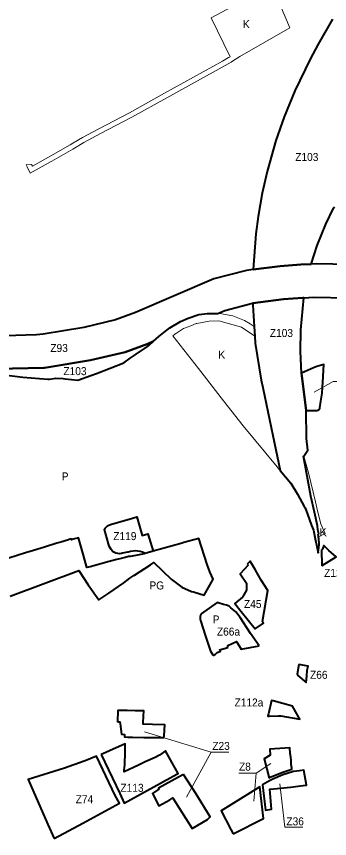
# Model space of a CAD drawing. Extents: x -650276 to -642489, y -1074311 to -1066658.
# Drawn here: x -648750 to -647810, y -1070673 to -1068210 of the extents above; entities that cross this region are included whole.
import ezdxf

# ---------------------------------------------------------------- set-up
doc = ezdxf.new("R2010")
doc.units = 0
doc.header["$LTSCALE"] = 9.6
for name, color, linetype, lineweight in [('2', 7, 'Continuous', 40), ('3', 7, 'Continuous', 40), ('44', 7, 'Continuous', 40), ('45', 7, 'Continuous', 40), ('46', 7, 'Continuous', 13), ('47', 7, 'Continuous', 13), ('48', 7, 'Continuous', 35), ('59', 7, 'Continuous', 13), ('60', 7, 'Continuous', 35)]:
    doc.layers.add(name, color=color, linetype=linetype, lineweight=lineweight)

msp = doc.modelspace()

# ---------------------------------------------------------------- linework, layer by layer
at = {"layer": '2'}
for points in [[(-648338.933, -1069812.492), (-648363.563, -1069819.352), (-648371.093, -1069815.602), (-648377.983, -1069813.332), (-648385.093, -1069811.952), (-648392.333, -1069811.482), (-648399.563, -1069811.922), (-648406.723, -1069813.272), (-648414.54, -1069815.288), (-648415.873, -1069815.632), (-648430.764, -1069818.704), (-648433.853, -1069819.342), (-648439.773, -1069820.012), (-648445.683, -1069819.552), (-648451.413, -1069818.022), (-648456.763, -1069815.432), (-648461.523, -1069811.902), (-648465.553, -1069807.532), (-648468.703, -1069802.482), (-648470.853, -1069796.942), (-648480.15, -1069765.358), (-648485.323, -1069747.432), (-648485.023, -1069746.592), (-648483.157, -1069743.818), (-648481.673, -1069741.612), (-648477.273, -1069737.482), (-648475.905, -1069736.566), (-648472.283, -1069734.142), (-648464.333, -1069730.932), (-648439.683, -1069724.232), (-648401.171, -1069713.196), (-648388.514, -1069709.779), (-648372.522, -1069765.283), (-648354.898, -1069760.328)], [(-647833.172, -1069855.944), (-647833.172, -1069855.944), (-647831.62, -1069854.99), (-647789.55, -1069829.12), (-647811.83, -1069810.39), (-647827.16, -1069795.32), (-647831.32, -1069806.56), (-647833.91, -1069808.91), (-647833.2, -1069854.15)]]:
    msp.add_lwpolyline(points, close=True, dxfattribs=at)
at = {"layer": '3'}
msp.add_lwpolyline([(-648495.666, -1070421.476), (-648439.409, -1070538.729), (-648425.835, -1070567.021), (-648267.801, -1070480.55), (-648263.859, -1070478.393), (-648282.01, -1070446.35), (-648302.01, -1070411.05), (-648320.24, -1070423.64), (-648332.97, -1070430.18), (-648362.79, -1070443.63), (-648363.1, -1070443.1), (-648383.61, -1070453.86), (-648426.05, -1070473.34), (-648425.71, -1070468.87), (-648424.47, -1070452.7), (-648423.56, -1070413.35), (-648423.005, -1070389.357), (-648469.77, -1070410.47), (-648481.18, -1070415.62)], close=True, dxfattribs=at)
at = {"layer": '44'}
for points in [[(-647801.168, -1068218.237), (-647843.6, -1068292.629), (-647868.214, -1068337.803), (-647914.339, -1068432.512), (-647946.187, -1068510.254), (-647971.074, -1068581.98), (-647997.27, -1068674.747), (-648011.775, -1068739.718), (-648023.914, -1068809.332), (-648030.73, -1068861.213), (-648038.596, -1068968.281), (-647958.168, -1068957.73)], [(-647864.531, -1068951.823), (-647846.989, -1068896.545), (-647820.883, -1068832.117), (-647797.632, -1068784.713), (-647795.185, -1068780.485)], [(-648058.764, -1068970.927), (-648156.739, -1068996.273), (-648392.002, -1069097.554), (-648451.865, -1069119.456), (-648547.243, -1069141.81), (-648668.959, -1069161.838), (-648688.912, -1069163.603), (-648721.315, -1069164.952), (-648781.015, -1069167.44)], [(-647749.978, -1068953.416), (-647850.043, -1068951.099), (-647864.531, -1068951.823), (-647895.901, -1068953.392), (-647958.168, -1068957.73), (-648038.596, -1068968.281), (-648038.596, -1068968.281), (-648038.746, -1068968.301), (-648058.764, -1068970.927)], [(-647958.168, -1068957.73), (-647895.901, -1068953.392), (-647864.531, -1068951.823)], [(-648665.007, -1069262.694), (-648527.693, -1069239.938), (-648423.173, -1069215.44), (-648354.978, -1069190.492), (-648338.523, -1069183.389), (-648322.14, -1069168.56), (-648306.83, -1069156.57), (-648289.25, -1069142.79), (-648257.5, -1069124.41), (-648234.22, -1069113.6), (-648202.46, -1069103.3), (-648175.65, -1069099.64), (-648144.866, -1069099.987), (-648124.327, -1069091.181), (-648040.705, -1069069.547), (-648040.456, -1069069.483)], [(-648040.456, -1069069.483), (-648040.537, -1069075.531), (-648036.291, -1069139.458), (-648034.421, -1069167.61)], [(-648040.456, -1069069.483), (-648039.666, -1069069.279), (-647948.18, -1069057.276)], [(-647948.18, -1069057.276), (-648039.666, -1069069.279), (-648040.456, -1069069.483)], [(-647948.18, -1069057.276), (-647889.927, -1069053.218), (-647886.615, -1069053.052)], [(-647886.615, -1069053.052), (-647889.927, -1069053.218), (-647948.18, -1069057.276)], [(-647887.087, -1069527.229), (-647878.73, -1069515.45), (-647874.75, -1069509.84), (-647878.93, -1069475.09), (-647880.326, -1069390.832), (-647893.553, -1069279.021), (-647896.67, -1069213.573), (-647896.362, -1069149.171), (-647886.615, -1069053.052)], [(-647886.615, -1069053.052), (-647856.541, -1069051.548), (-647756.441, -1069053.207), (-647708.401, -1069056.275), (-647511.94, -1069076.703), (-647426.417, -1069084.624), (-647344.902, -1069091.02), (-647270.522, -1069094.255), (-647197.498, -1069094.255), (-647123.648, -1069091.043), (-647065.688, -1069087.73)], [(-648034.421, -1069167.61), (-648033, -1069189), (-648015, -1069300), (-648010.092, -1069322.087), (-647980.331, -1069465.915), (-647958.34, -1069570.699), (-647925.99, -1069608.57)], [(-648354.978, -1069190.492), (-648423.173, -1069215.44), (-648527.693, -1069239.938), (-648652.716, -1069260.657)], [(-648526.15, -1069286.21), (-648508.95, -1069280.01), (-648427.08, -1069247.75), (-648407.73, -1069233.88), (-648389.91, -1069221.86), (-648355.81, -1069198.88), (-648351.77, -1069195.88), (-648338.523, -1069183.389), (-648354.978, -1069190.492)], [(-648918.889, -1069268.875), (-648761.189, -1069265.035), (-648666.827, -1069262.738), (-648665.007, -1069262.694)], [(-648666.827, -1069262.738), (-648761.189, -1069265.035), (-648918.889, -1069268.875), (-648909.86, -1069270.02), (-648861.49, -1069275.34), (-648785.92, -1069284.2), (-648730.66, -1069290.43), (-648730.66, -1069290.43), (-648655.53, -1069297.18), (-648650.06, -1069296.39), (-648636.85, -1069294.49)], [(-648652.716, -1069260.657), (-648665.007, -1069262.694), (-648666.827, -1069262.738)], [(-648636.85, -1069294.49), (-648630.82, -1069293.63), (-648609.425, -1069295.033), (-648603.228, -1069295.53), (-648565.18, -1069299.46), (-648526.15, -1069286.21)], [(-647865.69, -1069647.32), (-647887.649, -1069528.021), (-647887.087, -1069527.229)], [(-647925.99, -1069608.57), (-647906.16, -1069641.48), (-647885.665, -1069678.788), (-647885.663, -1069678.794), (-647883.51, -1069682.71), (-647875.82, -1069701.85)], [(-647842.438, -1069760.647), (-647845.086, -1069748.753), (-647846.484, -1069736.663), (-647855.158, -1069695.232), (-647865.69, -1069647.32)], [(-647875.82, -1069701.85), (-647864.19, -1069735.12), (-647858.44, -1069749.43), (-647852.63, -1069775.7), (-647850.66, -1069785.74), (-647849.165, -1069793.367), (-647843.74, -1069817.63), (-647841.402, -1069792.351)], [(-647841.402, -1069792.351), (-647842.489, -1069773.282), (-647842.622, -1069770.956), (-647843.337, -1069769.013), (-647843.443, -1069768.293), (-647843.458, -1069768.256), (-647843.449, -1069768.252), (-647844.371, -1069761.991), (-647842.438, -1069760.647)]]:
    msp.add_lwpolyline(points, dxfattribs=at)
msp.add_lwpolyline([(-647860.52, -1069390.72), (-647848.24, -1069390.65), (-647845.25, -1069390.07), (-647843.41, -1069389.23), (-647841.81, -1069387.99), (-647840.42, -1069386.51), (-647839.4, -1069384.73), (-647838.79, -1069382.86), (-647836.2, -1069362.68), (-647832.29, -1069338.58), (-647832.29, -1069338.58), (-647831.19, -1069320.69), (-647830.23, -1069305.38), (-647826.928, -1069253.199), (-647848.17, -1069259.21), (-647858.37, -1069263.03), (-647893.553, -1069279.017), (-647880.326, -1069390.832)], close=True, dxfattribs=at)
at = {"layer": '44', "lineweight": 13}
msp.add_lwpolyline([(-647751.811, -1069303.761), (-647798.61, -1069303.761), (-647856.005, -1069335.572)], dxfattribs=at)
msp.add_lwpolyline([(-647751.811, -1069303.761), (-647798.61, -1069303.761), (-647856.005, -1069335.572)], dxfattribs=at)
at = {"layer": '44'}
msp.add_arc((-648354.978, -1069190.492), 0.000000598, 264.13978, 298.69712, dxfattribs=at)
at = {"layer": '45'}
for points in [[(-648767.83, -1069946.87), (-648562.242, -1069870.301), (-648533.79, -1069913.49), (-648502.048, -1069957.969), (-648472.6, -1069937.81), (-648426.82, -1069906.88), (-648409.44, -1069893.25), (-648396.87, -1069885.43), (-648395.03, -1069884.22), (-648347.06, -1069853), (-648337.48, -1069846.531), (-648285.62, -1069895.71), (-648253.13, -1069919.7), (-648223.99, -1069932.96), (-648218.245, -1069934.595), (-648186.268, -1069943.697), (-648160.04, -1069897.73), (-648159.1, -1069896.39), (-648169.15, -1069873.81), (-648176.78, -1069851.74), (-648201.83, -1069773.86), (-648247.27, -1069786.64), (-648251.94, -1069787.95), (-648339.05, -1069812.45), (-648363.68, -1069819.31), (-648365.81, -1069819.9), (-648391.08, -1069825.45), (-648408.45, -1069827.83), (-648412.74, -1069828.72), (-648422.75, -1069830.78), (-648435.53, -1069834.44), (-648447.98, -1069837.44), (-648470.79, -1069843.51), (-648528.11, -1069858.73), (-648537.86, -1069861.22), (-648541.06, -1069849.78), (-648546.97, -1069828.68), (-648562.87, -1069771.85), (-648579.63, -1069776.66), (-648584.65, -1069778.1), (-648586.09, -1069775.75), (-648593.59, -1069778.06), (-648615.88, -1069784.93), (-648627.99, -1069788.67), (-648665.05, -1069799.99), (-648698.31, -1069810.16), (-648722.24, -1069817.54), (-648772.48, -1069832.83)], [(-648128.48, -1069971.7), (-648140.96, -1069968.01), (-648147.46, -1069966.19), (-648194.84, -1070000.49)], [(-648111.44, -1069977.32), (-648118.75, -1069974.53), (-648128.48, -1069971.7)], [(-648021.35, -1070096.14), (-648046.83, -1070058.62), (-648077.68, -1070011.06), (-648091.06, -1069994.07), (-648105.79, -1069981.56), (-648111.44, -1069977.32)], [(-648194.84, -1070000.49), (-648197.19, -1070003.94), (-648198.17, -1070008.05), (-648198.48, -1070012.3), (-648198.22, -1070016.4), (-648197.23, -1070020.37), (-648182.01, -1070067.11)], [(-648182.01, -1070067.11), (-648167.48, -1070111.75), (-648159.89, -1070122.49), (-648159.02, -1070123.71), (-648156.07, -1070123.54)], [(-648152.35, -1070121.05), (-648147.02, -1070116.35), (-648139.45, -1070112.79), (-648136.61, -1070111.97), (-648139.91, -1070107.48), (-648115.11, -1070101.26)], [(-648115.11, -1070101.26), (-648114.7, -1070094.68), (-648089.22, -1070083.27), (-648074.76, -1070106.17), (-648021.35, -1070096.14)], [(-648156.07, -1070123.54), (-648153.85, -1070122.38), (-648152.35, -1070121.05)]]:
    msp.add_lwpolyline(points, dxfattribs=at)
for points in [[(-648057.11, -1069851.12), (-648053.61, -1069854.64), (-648078.54, -1069880.01), (-648059.32, -1069908.27), (-648059.5, -1069929.52), (-648071.58, -1069950.39), (-648093.67, -1069969.42), (-648074.96, -1069993.46), (-648032.85, -1070044.73), (-648008.18, -1070028.25), (-648010.44, -1070023.66), (-648010.94, -1070022.65), (-647994.71, -1069930.53), (-648015.11, -1069898.98), (-648032.94, -1069867.46), (-648048.08, -1069841.95)], [(-648057.11, -1069851.12), (-648053.61, -1069854.64), (-648078.54, -1069880.01), (-648059.32, -1069908.27), (-648059.5, -1069929.52), (-648071.58, -1069950.39), (-648093.67, -1069969.42), (-648074.96, -1069993.46), (-648032.85, -1070044.73), (-648008.18, -1070028.25), (-648010.44, -1070023.66), (-648010.94, -1070022.65), (-647994.71, -1069930.53), (-648015.11, -1069898.98), (-648032.94, -1069867.46), (-648048.08, -1069841.95)], [(-647902.17, -1070151.64), (-647906.6, -1070180.65), (-647905.17, -1070184.5), (-647879.81, -1070206.08), (-647878.18, -1070186.33), (-647876.74, -1070168.88), (-647873.97, -1070156.58)], [(-647902.17, -1070151.64), (-647906.6, -1070180.65), (-647905.17, -1070184.5), (-647879.81, -1070206.08), (-647878.18, -1070186.33), (-647876.74, -1070168.88), (-647873.97, -1070156.58)], [(-647962.82, -1070305.9), (-647956.36, -1070305.77), (-647898.82, -1070315.51), (-647921.51, -1070276.76), (-647979.24, -1070260.71), (-647983.6, -1070259.5), (-647992.71, -1070300.01), (-647995.46, -1070306.55), (-647991.12, -1070306.46)], [(-648444.85, -1070324.47), (-648444.15, -1070289.16), (-648428.98, -1070288.92), (-648416.93, -1070288.85), (-648392.94, -1070289.25), (-648368.25, -1070289.71), (-648370.07, -1070325.94), (-648370.07, -1070329.902), (-648341.46, -1070330.48), (-648305.47, -1070331.23), (-648307.13, -1070365.57), (-648307.67, -1070371.78), (-648367.67, -1070371.16), (-648401.35, -1070370.5), (-648414.75, -1070370.24), (-648424.05, -1070370), (-648424.31, -1070362.21), (-648433.46, -1070361.94), (-648437.65, -1070328.8), (-648438.296, -1070324.598)], [(-648444.85, -1070324.47), (-648444.15, -1070289.16), (-648428.98, -1070288.92), (-648416.93, -1070288.85), (-648392.94, -1070289.25), (-648368.25, -1070289.71), (-648370.07, -1070325.94), (-648370.07, -1070329.902), (-648341.46, -1070330.48), (-648305.47, -1070331.23), (-648307.13, -1070365.57), (-648307.67, -1070371.78), (-648367.67, -1070371.16), (-648401.35, -1070370.5), (-648414.75, -1070370.24), (-648424.05, -1070370), (-648424.31, -1070362.21), (-648433.46, -1070361.94), (-648437.65, -1070328.8), (-648438.296, -1070324.598)], [(-647991.539, -1070492.016), (-647985.19, -1070488.804), (-647953.251, -1070475.276), (-647923.247, -1070465.749), (-647923.53, -1070462.75), (-647924.63, -1070451.09), (-647925.5, -1070439.63), (-647926.53, -1070429.76), (-647927.67, -1070418.74), (-647929.24, -1070401.97), (-647988.86, -1070405.95), (-647988.11, -1070423.93), (-648005.668, -1070434.145)], [(-648636.757, -1070673.431), (-648550.72, -1070626.869), (-648440.531, -1070567.236), (-648452.97, -1070544.21), (-648509.227, -1070426.957), (-648526.28, -1070433.85), (-648538.611, -1070438.388), (-648546.377, -1070441.246), (-648604.92, -1070462.79), (-648714.161, -1070496.376), (-648655.178, -1070631.294)], [(-647950.48, -1070482.79), (-647980.4, -1070495.463), (-647990.295, -1070500.352), (-648003.85, -1070508.218), (-648010.831, -1070512.588), (-648002, -1070588), (-647984.03, -1070585.46), (-647989.5, -1070525.73), (-647987.436, -1070525.508), (-647977.41, -1070524.43), (-647927.14, -1070519), (-647889.27, -1070514.92), (-647879.89, -1070513.91), (-647879.16, -1070513.83), (-647887.08, -1070468.54), (-647899.87, -1070470.04), (-647917.98, -1070472.47)], [(-648247.67, -1070481.57), (-648262.69, -1070489.67), (-648323.59, -1070522.48), (-648322.18, -1070525.44), (-648341.41, -1070538.42), (-648322.16, -1070575.76), (-648289.22, -1070557.15), (-648279.736, -1070551.783), (-648278.89, -1070553.14), (-648222.58, -1070643.48), (-648176.54, -1070616.09), (-648168.575, -1070607.847), (-648211, -1070538)], [(-648247.67, -1070481.57), (-648262.69, -1070489.67), (-648323.59, -1070522.48), (-648322.18, -1070525.44), (-648341.41, -1070538.42), (-648322.16, -1070575.76), (-648289.22, -1070557.15), (-648279.736, -1070551.783), (-648278.89, -1070553.14), (-648222.58, -1070643.48), (-648176.54, -1070616.09), (-648168.575, -1070607.847), (-648211, -1070538)], [(-648098.637, -1070659.682), (-648007.838, -1070612.851), (-648019, -1070518), (-648135.47, -1070590.61), (-648105.98, -1070645.91)]]:
    msp.add_lwpolyline(points, close=True, dxfattribs=at)
at = {"layer": '46'}
for p, q in [((-648165.109, -1070414.543), (-648239.52, -1070549.62)), ((-648165.109, -1070414.543), (-648239.52, -1070549.62)), ((-648030.462, -1070477.049), (-648036.992, -1070561.483)), ((-647944.293, -1070639.492), (-647959.279, -1070509.201)), ((-647890.215, -1070639.492), (-647944.293, -1070639.492)), ((-647890.215, -1070639.492), (-647904.43, -1070639.492))]:
    msp.add_line(p, q, dxfattribs=at)
for points in [[(-648112.329, -1070414.543), (-648165.109, -1070414.543), (-648364.98, -1070353.932)], [(-648112.329, -1070414.543), (-648165.109, -1070414.543), (-648364.98, -1070353.932)], [(-648081.63, -1070477.049), (-648030.462, -1070477.049), (-647985.902, -1070448.995)]]:
    msp.add_lwpolyline(points, dxfattribs=at)
at = {"layer": '47'}
msp.add_line((-648108.158, -1068330.583), (-648112.198, -1068333.037), dxfattribs=at)
for points in [[(-648101.42, -1068344.28), (-648079.33, -1068330.03), (-647929.45, -1068244.16), (-647971.35, -1068144.48), (-647982.969, -1068116.575), (-648165.28, -1068214.465), (-648108.158, -1068330.583)], [(-648112.198, -1068333.037), (-648112.92, -1068333.424), (-648131.034, -1068344.388), (-648305.242, -1068440.3), (-648410.111, -1068498.408), (-648503.768, -1068547.914), (-648551.041, -1068573.16)], [(-648547.25, -1068588.14), (-648496.73, -1068561.16), (-648402.97, -1068511.6), (-648297.99, -1068453.43), (-648123.53, -1068357.38), (-648105.49, -1068346.46), (-648101.42, -1068344.28)], [(-648551.041, -1068573.16), (-648580.062, -1068590.087), (-648588.022, -1068594.571), (-648653.034, -1068631.191), (-648701.568, -1068658.36), (-648703.816, -1068653.711), (-648720.238, -1068654.205)], [(-648720.238, -1068654.205), (-648717.32, -1068660.24), (-648708.14, -1068679.23), (-648645.69, -1068644.27), (-648643.654, -1068643.123), (-648580.66, -1068607.64), (-648547.25, -1068588.14)], [(-648036.291, -1069139.458), (-648040.537, -1069075.531), (-648040.5, -1069072.79), (-648040.705, -1069069.548), (-648124.327, -1069091.181), (-648144.866, -1069099.987)], [(-648144.866, -1069099.987), (-648139.27, -1069100.05), (-648100.37, -1069107.1), (-648100.37, -1069107.1), (-648065.16, -1069121.12)], [(-648065.16, -1069121.12), (-648048.06, -1069130.81), (-648036.291, -1069139.458)]]:
    msp.add_lwpolyline(points, dxfattribs=at)
for points in [[(-648127.77, -1069361.38), (-648068.71, -1069436.57), (-647967.53, -1069559.94), (-647958.214, -1069571.3), (-647980.331, -1069465.915), (-648010.092, -1069322.087), (-648015, -1069300), (-648033, -1069189), (-648034.421, -1069167.61), (-648073.66, -1069140.86), (-648141.92, -1069121.66), (-648171.14, -1069122.83), (-648207.77, -1069129.95), (-648209.89, -1069130.36), (-648226.51, -1069136.57), (-648248.14, -1069144.65), (-648268.87, -1069158.61), (-648270.92, -1069159.99), (-648275.19, -1069162.87), (-648280.1, -1069166.97), (-648203.01, -1069264.73)], [(-647845.086, -1069748.753), (-647842.438, -1069760.647), (-647844.371, -1069761.991), (-647843.337, -1069769.013), (-647822.54, -1069759.29), (-647830, -1069744.7), (-647835.76, -1069730.01), (-647845.85, -1069691.2), (-647852.44, -1069664.03), (-647873.43, -1069577.87), (-647887.087, -1069527.229), (-647865.69, -1069647.32), (-647855.158, -1069695.232), (-647846.484, -1069736.663)]]:
    msp.add_lwpolyline(points, close=True, dxfattribs=at)

# ---------------------------------------------------------------- texts
at = {"layer": '2', "width": 0.95}
for s, p in [('Z119', (-648458.914, -1069779.092)), ('Z129', (-647826.051, -1069889.189))]:
    msp.add_text(s, height=24, dxfattribs=at).set_placement(p)
at = {"layer": '44', "width": 0.95}
for s, p in [('Z103', (-647912.849, -1068643.055)), ('Z103', (-647989.032, -1069170.515)), ('Z103', (-647989.032, -1069170.515)), ('Z93', (-648647.673, -1069215.426)), ('Z93', (-648647.673, -1069215.426)), ('Z103', (-648608.542, -1069284.81)), ('Z103', (-648608.542, -1069284.81))]:
    msp.add_text(s, height=24, dxfattribs=at).set_placement(p)
at = {"layer": '46', "width": 0.95}
for s, p in [('Z45', (-648066.663, -1069982.614)), ('Z45', (-648066.663, -1069982.614)), ('Z66a', (-648147.889, -1070065.308)), ('Z66', (-647868.376, -1070194.801)), ('Z112a', (-648094.972, -1070277.658)), ('Z23', (-648161.708, -1070407.912)), ('Z23', (-648161.708, -1070407.912)), ('Z8', (-648081.661, -1070469.822)), ('Z74', (-648571.565, -1070567.472)), ('Z36', (-647939.415, -1070633.92)), ('Z36', (-647939.415, -1070633.92))]:
    msp.add_text(s, height=24, dxfattribs=at).set_placement(p)
at = {"layer": '48'}
for p in [(-648070.59, -1068244.82), (-648070.59, -1068244.82), (-648144.004, -1069235.577), (-648144.004, -1069235.577), (-647839.874, -1069767.492)]:
    msp.add_text('K', height=24, dxfattribs=at).set_placement(p)
at = {"layer": '59', "width": 0.95}
msp.add_text('Z113', height=24, dxfattribs=at).set_placement((-648437.324, -1070533.384))
msp.add_text('Z113', height=24, dxfattribs=at).set_placement((-648437.324, -1070533.384))
at = {"layer": '60'}
for s, width, p in [('P', 0.9, (-648612.658, -1069600.244)), ('PG', 0.95, (-648350.408, -1069926.995)), ('P', 0.9, (-648159.699, -1070028.97))]:
    msp.add_text(s, height=24, dxfattribs=dict(at, width=width)).set_placement(p)

doc.saveas('drawing.dxf')
